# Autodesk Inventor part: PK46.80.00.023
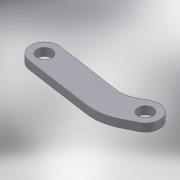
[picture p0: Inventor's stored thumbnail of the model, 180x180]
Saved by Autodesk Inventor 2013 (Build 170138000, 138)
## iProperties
Created: 2005-04
Part Number: PK46.80.00.023
Material: Steel, Mild
Document SubType Name: Modeling
Designer: salex
Manufacturer: Standard
Standards Organization: Custom
Density: 7.86 g/cm^3
Mass: 1542.86 g
Surface Area: 368.91 cm^2
Volume: 196.292 cm^3
Author: salex
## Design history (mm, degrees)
sketch "Эскиз5"
  geometry: L1 (3.953, 27.214)-(134.626, 8.233); L2 (163.933, 12.873)-(187.835, 24.663); L3 (-3.953, -27.214)-(128.257, -46.419); L4 (186.87, -37.14)-(212.165, -24.663); C1 r 15 at (0, 0); C2 r 15 at (200, 0); A1 r 27.5 centre (0, 0) between (3.953, 27.214) and (-3.953, -27.214); A2 r 27.5 centre (200, 0) between (212.165, -24.663) and (187.835, 24.663); A3 r 50 centre (141.813, 57.714) between (134.626, 8.233) and (163.933, 12.873); A4 r 100 centre (142.632, 52.543) between (128.257, -46.419) and (186.87, -37.14); 1 further point
  constraints: 8 end point, 8 point on circle, 8 tangent, 6 centre point, 2 coincident, 2 equal radius, 2 parallel, 2 point on line, 1 other
  dimensions: "d29" = 30 diameter of C1; "d30" = 0 vertical distance of C2.centre C1.centre; "d31" = 200 distance of C2.centre C1.centre; "d32" = 6 vertical distance of point (150, 6) C1.centre; "d33" = 27.5 radius of A1; "d34" = 150 horizontal distance of point (150, 6) C1.centre; "d35" = 50 radius of A3; "d36" = 100 radius of A4
extrude "Выдавливание5" new body sketch "Эскиз5" distance "d37" = 16; taper "d38" = 0 deg
body "Solid1"
